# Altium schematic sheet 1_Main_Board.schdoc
size 431 x 309 mm; Symbol: Sheet-Symbol_A3; Device: Sheet-Symbol_A3; Convert to PCB: yes; Add into BOM: yes; Company: PhantomRumor; Drawed: PhantomR; @Project Name: 【三键侧透光小键盘】CH552G; @Page Count: 1; @Update Date: 2023-03-01; @Create Date: 2022-08-11; @Schematic Name: SCH_CH552G; @Page No: 1; @Page Name: Main_Board
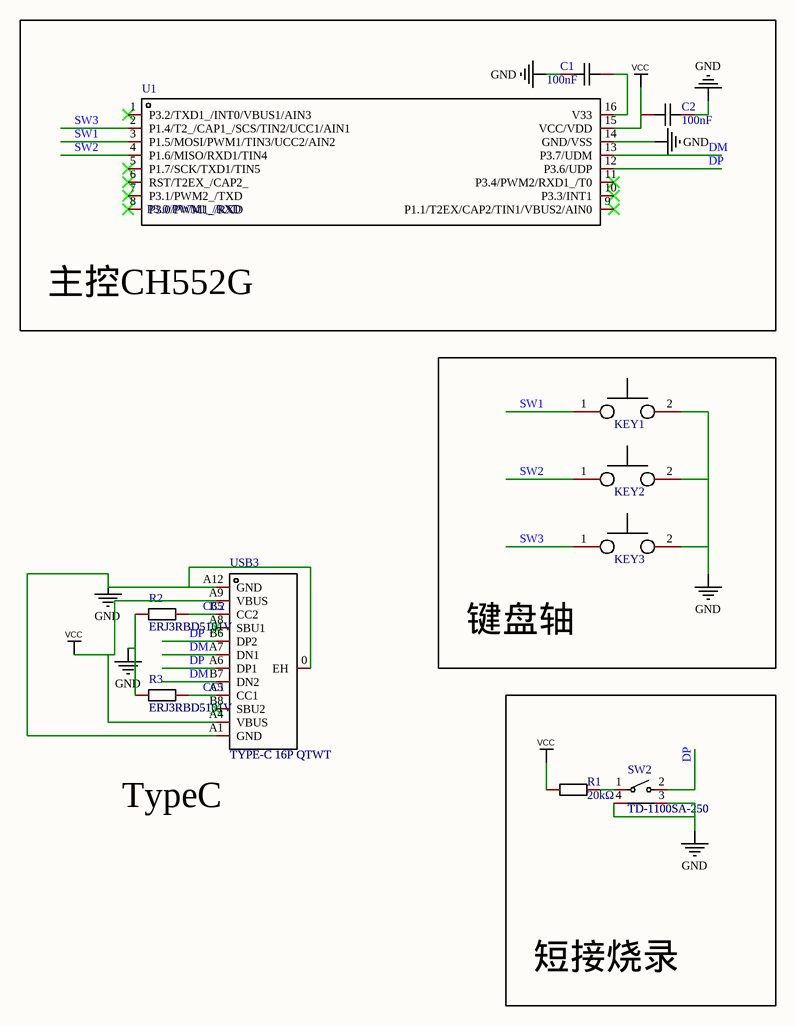
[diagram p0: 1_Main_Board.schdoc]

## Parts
C1  value 100nF  [C0603]  (hidden comment: CC0603KRX7R9BB104)
C2  value 100nF  [C0603]  (hidden comment: CC0603KRX7R9BB104)
KEY1  五脚无灯热插拔轴体  [五脚无灯热插拔轴体]  (value not drawn)
KEY2  五脚无灯热插拔轴体  [五脚无灯热插拔轴体]  (value not drawn)
KEY3  五脚无灯热插拔轴体  [五脚无灯热插拔轴体]  (value not drawn)
R1  value 20kΩ  [R0603]  (hidden comment: 0603WAF2002T5E)
R2  ERJ3RBD5101V  [R0603]
R3  ERJ3RBD5101V  [R0603]
SW2  TD-1100SA-250  [SW-SMD_TD-1100SA-250]
U1  NAME: P3.0/PWM1_/RXD  [SOP-16_L10.0-W3.9-P1.27-LS6.0-BL]  (hidden comment: CH552G)
USB3  TYPE-C 16P QTWT  [USB-TYPE-C-SMD_TYPE-C-16P-QTWT]

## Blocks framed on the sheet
主控CH552G: C1 C2 U1
键盘轴: KEY1-KEY3
短接烧录: R1 SW2

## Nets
GND: C1.1 C2.2 KEY1.2 KEY2.2 KEY3.2 R2.1 R3.1 SW2.3 SW2.4 U1.14(GND/VSS) USB3.0(EH) USB3.A1(GND) USB3.A12(GND)
VCC: C2.1 R1.2 U1.15(VCC/VDD) USB3.A4(VBUS) USB3.A9(VBUS)
CC1: R3.2 USB3.A5(CC1)
CC2: R2.2 USB3.B5(CC2)
DM: U1.13(P3.7/UDM) USB3.A7(DN1) USB3.B7(DN2)
DP: SW2.2 U1.12(P3.6/UDP) USB3.A6(DP1) USB3.B6(DP2)
SW1: KEY1.1 U1.3(P1.5/MOSI/PWM1/TIN3/UCC2/AIN2)
SW2: KEY2.1 U1.4(P1.6/MISO/RXD1/TIN4)
SW3: KEY3.1 U1.2(P1.4/T2_/CAP1_/SCS/TIN2/UCC1/AIN1)
NetC1_2: C1.2 U1.16(V33)
NetR1_1: R1.1 SW2.1

Not connected (* = marked no-connect by the designer): U1 1(P3.2/TXD1_/INT0/VBUS1/AIN3)* 5(P1.7/SCK/TXD1/TIN5)* 6(RST/T2EX_/CAP2_)* 7(P3.1/PWM2_/TXD)* 8(P3.0/PWM1_/RXD)* 9(P1.1/T2EX/CAP2/TIN1/VBUS2/AIN0)* 10(P3.3/INT1)* 11(P3.4/PWM2/RXD1_/T0)*; USB3 A8(SBU1)* B8(SBU2)*

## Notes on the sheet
- (near USB3) TypeC

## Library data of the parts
C1 C2 = CC0603KRX7R9BB104: 容值:100nF;精度:±10%;额定电压:50V;材质(温度系数):X7R;; Manufacturer: YAGEO(国巨); Add into BOM: yes; Tolerance: ±10%; Voltage Rated: 50V; Temperature Coefficient: X7R
KEY1-KEY3 = 五脚无灯热插拔轴体: Add into BOM: no; Convert to PCB: yes
R1 = 0603WAF2002T5E: 电阻类型:厚膜电阻;阻值:20kΩ;精度:±1%;功率:100mW;温度系数:±100ppm/;最大工作电压:75V;工作温度范围:-55~+155;; Manufacturer: UNI-ROYAL(厚声); Add into BOM: yes; Tolerance: ±1%; Power(Watts): 100mW; Overload Voltage (Max): 75V
R2 R3 = ERJ3RBD5101V: Manufacturer: PANASONIC(松下); Symbol: ERJ-3RBD5101V; Add into BOM: yes
SW2 = TD-1100SA-250: Manufacturer: DEALON(德艺隆); Add into BOM: yes
U1 = CH552G: CPU内核:51系列;CPU最大主频:24MHz;工作电压范围:3.3V~5V;内部振荡器:有;外部时钟频率范围:6MHz~25MHz;程序 FLASH容量:16KB;RAM总容量:1.25KB;EEPROM/数据 FLASH容量:128Byte;GPIO端口数量:-;ADC(单元数/通道数/位数):1@x4ch/8bit;DAC(单元数/通道数/位数):-;(E)PWM(单元数/通道数/位数):2@x8bit;8位Timer数量:-;16位Timer数量:3;32位Timer数量:-;内部比较器数量:-; Manufacturer: WCH(南京沁恒); Add into BOM: yes; CPU Core: 51系列; Maximum Frequency: 24MHz; Internal Oscillator: 有; Program FLASH Size: 16KB; RAM Size: 1.25KB; 16Bit Timer Number: 3; U(S)ART Number: 2; (Q)SPI Number: 1; USB (H/D/OTG): 全速USB Device; Peripherals / Functions / Protocol Stacks: DMA；看门狗；CCP捕获/比较；触控按键
USB3 = TYPE-C 16P QTWT: 连接器类型：Type-C 公母：母座 触点数量：16 端口数量：1 安装方式：立贴 额定电流/电压：3A 5V工作温度范围：-25℃~+85℃ Type-C母座 16PIN四脚全贴片卧贴; Manufacturer: SHOU HAN(首韩); Add into BOM: yes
